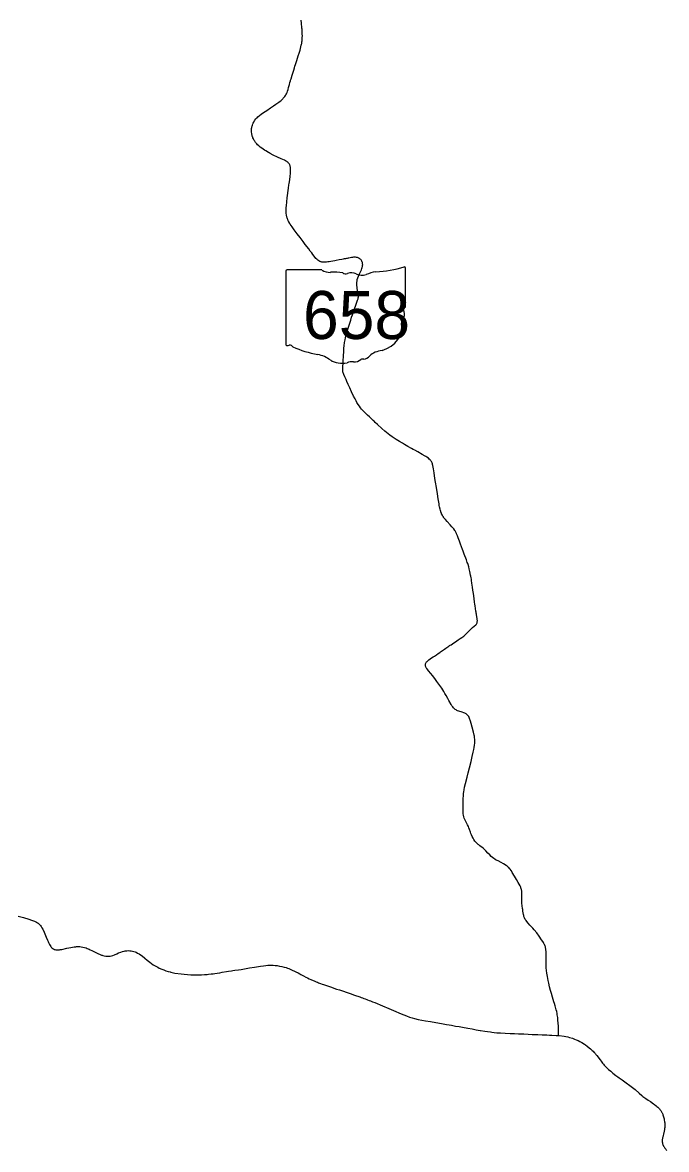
# Model space of a CAD drawing. Extents: x 1913970 to 2397567, y 78841 to 829347.
# Drawn here: x 2199640 to 2214681, y 744108 to 770418 of the extents above; entities that cross this region are included whole.
import ezdxf

# ---------------------------------------------------------------- set-up
doc = ezdxf.new("R2010")
doc.units = 0
doc.layers.add('GM_X_State_Route', color=7, linetype='Continuous')
doc.layers.add('GM_X_State_Shield', color=7, linetype='Continuous')

msp = doc.modelspace()

# ---------------------------------------------------------------- linework, layer by layer
at = {"layer": 'GM_X_State_Route'}
for points in [[(2204992, 767950), (2204993, 767962), (2204997, 767980), (2205001, 767995), (2205009, 768020), (2205022, 768056), (2205028, 768071), (2205040, 768096), (2205047, 768108), (2205061, 768130), (2205069, 768140), (2205090, 768167), (2205109, 768188), (2205118, 768197), (2205139, 768218), (2205172, 768247), (2205212, 768278), (2205271, 768318), (2205345, 768368), (2205432, 768425), (2205502, 768472), (2205559, 768511), (2205626, 768559), (2205657, 768583), (2205679, 768601), (2205701, 768620), (2205720, 768638), (2205731, 768650), (2205747, 768666), (2205765, 768689), (2205781, 768711), (2205793, 768732), (2205806, 768756), (2205818, 768785), (2205830, 768817), (2205843, 768858), (2205856, 768901), (2205874, 768970), (2205886, 769015), (2205897, 769054), (2205902, 769071), (2205911, 769101), (2205937, 769187), (2205959, 769256), (2205975, 769308), (2205991, 769361), (2206003, 769401), (2206016, 769440), (2206045, 769529), (2206080, 769637), (2206101, 769703), (2206123, 769776), (2206144, 769851), (2206152, 769888), (2206158, 769916), (2206161, 769930), (2206166, 769967), (2206168, 769988), (2206172, 770028), (2206175, 770067), (2206176, 770110), (2206175, 770145), (2206175, 770176), (2206174, 770210), (2206172, 770242), (2206169, 770267), (2206167, 770289), (2206165, 770309), (2206163, 770328), (2206157, 770375), (2206153, 770405), (2206146, 770471)], [(2210127, 757400), (2210123, 757426), (2210118, 757454), (2210111, 757494), (2210107, 757517), (2210090, 757598), (2210075, 757664), (2210062, 757712), (2210046, 757763), (2210038, 757789), (2210029, 757815), (2210007, 757876), (2209958, 758005), (2209933, 758073), (2209917, 758117), (2209895, 758175), (2209871, 758239), (2209847, 758306), (2209819, 758384), (2209800, 758432), (2209779, 758480), (2209775, 758488), (2209759, 758522), (2209742, 758551), (2209737, 758559), (2209714, 758594), (2209697, 758617), (2209678, 758640), (2209671, 758648), (2209631, 758692), (2209557, 758768), (2209517, 758812), (2209498, 758835), (2209491, 758844), (2209475, 758866), (2209469, 758877), (2209453, 758904), (2209447, 758914), (2209430, 758949), (2209426, 758959), (2209412, 758994), (2209409, 759001), (2209402, 759024), (2209393, 759058), (2209380, 759113), (2209375, 759144), (2209368, 759183), (2209350, 759299), (2209331, 759416), (2209307, 759565), (2209287, 759688), (2209274, 759774), (2209254, 759902), (2209238, 759996), (2209232, 760039), (2209224, 760076), (2209218, 760102), (2209213, 760118), (2209207, 760135), (2209199, 760152), (2209190, 760169), (2209181, 760181), (2209171, 760195), (2209163, 760205), (2209141, 760226), (2209119, 760245), (2209086, 760268), (2209058, 760287), (2209042, 760297), (2208975, 760336), (2208872, 760393), (2208801, 760431), (2208761, 760453), (2208727, 760472), (2208636, 760523), (2208564, 760564), (2208514, 760594), (2208446, 760635), (2208366, 760686), (2208275, 760745), (2208218, 760784), (2208181, 760812), (2208140, 760845), (2208103, 760877), (2208030, 760943), (2207931, 761034), (2207879, 761083), (2207850, 761110), (2207831, 761128), (2207743, 761212), (2207698, 761255), (2207653, 761298), (2207595, 761356), (2207561, 761392), (2207534, 761425), (2207508, 761460), (2207479, 761503), (2207451, 761548), (2207430, 761585), (2207407, 761629), (2207373, 761696), (2207325, 761797), (2207283, 761889), (2207247, 761970), (2207217, 762036), (2207196, 762084), (2207169, 762147), (2207147, 762199), (2207137, 762222), (2207131, 762238), (2207124, 762265), (2207123, 762280), (2207121, 762292), (2207119, 762335), (2207122, 762390), (2207126, 762456), (2207132, 762544), (2207136, 762603), (2207138, 762639), (2207143, 762737), (2207146, 762790), (2207148, 762813), (2207154, 762871), (2207163, 762946), (2207174, 763011), (2207182, 763055), (2207194, 763104), (2207226, 763212), (2207306, 763471), (2207327, 763538), (2207346, 763597), (2207374, 763678), (2207416, 763800), (2207432, 763846), (2207465, 763935), (2207476, 763968), (2207482, 763993), (2207485, 764015), (2207486, 764034), (2207485, 764047), (2207482, 764068), (2207472, 764125), (2207456, 764212), (2207453, 764241), (2207449, 764280), (2207447, 764321), (2207449, 764349), (2207450, 764362), (2207453, 764382), (2207460, 764419), (2207472, 764458), (2207487, 764498), (2207510, 764551), (2207554, 764643), (2207566, 764675), (2207574, 764696), (2207576, 764706), (2207581, 764725), (2207583, 764735), (2207584, 764750), (2207585, 764759), (2207584, 764781), (2207582, 764797), (2207580, 764808), (2207578, 764816), (2207574, 764827), (2207568, 764843), (2207559, 764859), (2207554, 764866), (2207547, 764876), (2207539, 764886), (2207529, 764895), (2207519, 764903), (2207513, 764907), (2207505, 764912), (2207498, 764916), (2207482, 764923), (2207464, 764929), (2207441, 764934), (2207419, 764937), (2207394, 764937), (2207372, 764937), (2207346, 764933), (2207324, 764929), (2207292, 764924), (2207261, 764918), (2207243, 764915), (2207224, 764911), (2207205, 764908), (2207182, 764904), (2207156, 764899), (2207133, 764894), (2207102, 764888), (2207035, 764875), (2206967, 764862), (2206931, 764855), (2206887, 764848), (2206844, 764840), (2206799, 764832), (2206768, 764828), (2206739, 764825), (2206705, 764822), (2206683, 764821), (2206659, 764822), (2206634, 764825), (2206618, 764829), (2206610, 764831), (2206604, 764833), (2206593, 764837), (2206582, 764842), (2206566, 764851), (2206558, 764856), (2206537, 764870), (2206521, 764884), (2206512, 764892), (2206492, 764913), (2206453, 764961), (2206424, 765000), (2206395, 765039), (2206378, 765061), (2206362, 765082), (2206324, 765131), (2206245, 765239), (2206196, 765304), (2206124, 765400), (2206057, 765488), (2205986, 765582), (2205937, 765648), (2205912, 765682), (2205892, 765712), (2205883, 765725), (2205860, 765764), (2205855, 765773), (2205850, 765783), (2205846, 765792), (2205840, 765806), (2205835, 765817), (2205826, 765839), (2205820, 765858), (2205815, 765873), (2205811, 765889), (2205806, 765909), (2205803, 765928), (2205799, 765957), (2205796, 765982), (2205795, 765998), (2205795, 766020), (2205798, 766066), (2205799, 766099), (2205803, 766141), (2205824, 766326), (2205853, 766549), (2205864, 766627), (2205868, 766659), (2205880, 766746), (2205891, 766832), (2205899, 766896), (2205902, 766950), (2205902, 766965), (2205901, 766994), (2205899, 767022), (2205897, 767039), (2205893, 767058), (2205889, 767073), (2205885, 767085), (2205880, 767097), (2205874, 767109), (2205866, 767122), (2205854, 767137), (2205843, 767149), (2205835, 767156), (2205827, 767162), (2205815, 767171), (2205795, 767183), (2205784, 767190), (2205759, 767202), (2205682, 767237), (2205592, 767278), (2205498, 767325), (2205426, 767361), (2205398, 767375), (2205385, 767382), (2205320, 767419), (2205292, 767437), (2205257, 767461), (2205227, 767482), (2205191, 767510), (2205156, 767541), (2205130, 767566), (2205110, 767588), (2205091, 767610), (2205084, 767620), (2205073, 767634), (2205065, 767645), (2205050, 767667), (2205042, 767682), (2205032, 767700), (2205022, 767724), (2205016, 767740), (2205011, 767752), (2205004, 767776), (2205001, 767788), (2204997, 767804), (2204993, 767824), (2204989, 767855), (2204988, 767889), (2204989, 767921), (2204990, 767938), (2204992, 767950)], [(2212155, 746766), (2212155, 746786), (2212155, 746844), (2212156, 746902), (2212156, 746954), (2212155, 746989), (2212151, 747056), (2212147, 747125), (2212140, 747185), (2212130, 747253), (2212126, 747283), (2212117, 747327), (2212108, 747366), (2212081, 747463), (2212065, 747514), (2212051, 747557), (2212021, 747660), (2211994, 747746), (2211974, 747821), (2211952, 747906), (2211932, 747990), (2211919, 748054), (2211901, 748148), (2211888, 748227), (2211880, 748285), (2211874, 748347), (2211869, 748410), (2211867, 748481), (2211867, 748592), (2211868, 748645), (2211867, 748720), (2211864, 748773), (2211862, 748788), (2211859, 748810), (2211855, 748828), (2211852, 748837), (2211846, 748855), (2211833, 748889), (2211825, 748904), (2211818, 748919), (2211805, 748941), (2211793, 748960), (2211764, 749003), (2211707, 749085), (2211650, 749164), (2211594, 749232), (2211558, 749274), (2211488, 749348), (2211447, 749391), (2211416, 749430), (2211400, 749451), (2211382, 749480), (2211365, 749515), (2211359, 749530), (2211353, 749550), (2211347, 749567), (2211343, 749590), (2211335, 749630), (2211328, 749674), (2211322, 749716), (2211320, 749729), (2211310, 749804), (2211304, 749848), (2211301, 749887), (2211299, 749923), (2211300, 749965), (2211302, 750017), (2211305, 750078), (2211304, 750112), (2211303, 750129), (2211301, 750145), (2211298, 750162), (2211294, 750177), (2211289, 750194), (2211282, 750212), (2211276, 750228), (2211262, 750259), (2211217, 750342), (2211180, 750408), (2211131, 750491), (2211079, 750576), (2211059, 750609), (2211051, 750621), (2211030, 750651), (2211018, 750666), (2210997, 750691), (2210987, 750700), (2210979, 750707), (2210971, 750714), (2210956, 750725), (2210934, 750740), (2210877, 750774), (2210822, 750804), (2210746, 750843), (2210706, 750864), (2210683, 750877), (2210675, 750882), (2210651, 750899), (2210620, 750923), (2210588, 750950), (2210552, 750984), (2210509, 751028), (2210462, 751078), (2210430, 751110), (2210396, 751139), (2210322, 751198), (2210295, 751220), (2210286, 751227), (2210256, 751254), (2210229, 751281), (2210206, 751309), (2210184, 751341), (2210163, 751376), (2210144, 751412), (2210125, 751454), (2210112, 751488), (2210101, 751517), (2210082, 751575), (2210068, 751614), (2210054, 751647), (2210036, 751684), (2209986, 751780), (2209971, 751813), (2209958, 751843), (2209948, 751873), (2209939, 751909), (2209934, 751944), (2209932, 751982), (2209930, 752039), (2209930, 752117), (2209932, 752196), (2209935, 752291), (2209938, 752370), (2209941, 752415), (2209946, 752454), (2209953, 752502), (2209967, 752569), (2209989, 752655), (2210024, 752801), (2210048, 752903), (2210077, 753020), (2210116, 753168), (2210145, 753280), (2210169, 753385), (2210182, 753443), (2210191, 753490), (2210200, 753549), (2210203, 753592), (2210205, 753635), (2210204, 753674), (2210204, 753687), (2210200, 753720), (2210198, 753737), (2210195, 753756), (2210190, 753781), (2210172, 753853), (2210141, 753970), (2210118, 754054), (2210102, 754110), (2210082, 754169), (2210072, 754194), (2210061, 754214), (2210051, 754228), (2210035, 754248), (2210017, 754264), (2210000, 754277), (2209975, 754290), (2209949, 754300), (2209912, 754314), (2209831, 754338), (2209800, 754350), (2209787, 754356), (2209765, 754368), (2209748, 754379), (2209728, 754395), (2209705, 754418), (2209689, 754439), (2209670, 754465), (2209653, 754493), (2209601, 754587), (2209574, 754634), (2209535, 754704), (2209506, 754754), (2209480, 754797), (2209457, 754836), (2209431, 754877), (2209389, 754937), (2209319, 755034), (2209271, 755103), (2209216, 755173), (2209177, 755221), (2209122, 755286), (2209104, 755306), (2209082, 755337), (2209071, 755353), (2209063, 755370), (2209058, 755379), (2209055, 755390), (2209052, 755404), (2209051, 755416), (2209051, 755426), (2209053, 755442), (2209058, 755458), (2209066, 755474), (2209076, 755489), (2209089, 755504), (2209104, 755519), (2209127, 755537), (2209158, 755559), (2209194, 755583), (2209230, 755606), (2209262, 755627), (2209285, 755642), (2209309, 755659), (2209350, 755686), (2209387, 755712), (2209406, 755725), (2209429, 755741), (2209497, 755787), (2209531, 755812), (2209572, 755840), (2209595, 755856), (2209616, 755871), (2209628, 755880), (2209649, 755893), (2209680, 755914), (2209714, 755936), (2209754, 755961), (2209819, 756003), (2209864, 756034), (2209902, 756062), (2209944, 756095), (2209977, 756124), (2210013, 756154), (2210047, 756190), (2210152, 756292), (2210191, 756326), (2210227, 756358), (2210241, 756374), (2210250, 756386), (2210257, 756404), (2210261, 756421), (2210262, 756428), (2210263, 756435), (2210264, 756450), (2210264, 756460), (2210263, 756472), (2210261, 756489), (2210258, 756510), (2210255, 756526), (2210253, 756540), (2210249, 756561), (2210247, 756573), (2210241, 756605), (2210238, 756626), (2210234, 756649), (2210231, 756674), (2210221, 756740), (2210214, 756796), (2210206, 756842), (2210200, 756889), (2210187, 756973), (2210171, 757090), (2210160, 757167), (2210151, 757239), (2210145, 757283), (2210138, 757332), (2210129, 757393), (2210127, 757400)], [(2199542, 749556), (2199662, 749521), (2199785, 749483), (2199853, 749460), (2199894, 749444), (2199918, 749435), (2199934, 749428), (2199967, 749412), (2199988, 749400), (2200003, 749390), (2200025, 749372), (2200039, 749357), (2200058, 749336), (2200074, 749313), (2200083, 749300), (2200095, 749279), (2200112, 749247), (2200143, 749182), (2200162, 749140), (2200194, 749061), (2200224, 748991), (2200236, 748963), (2200246, 748937), (2200253, 748923), (2200270, 748890), (2200284, 748867), (2200299, 748845), (2200309, 748831), (2200320, 748820), (2200327, 748813), (2200348, 748798), (2200357, 748792), (2200368, 748785), (2200379, 748780), (2200396, 748775), (2200420, 748769), (2200446, 748767), (2200468, 748767), (2200482, 748768), (2200505, 748770), (2200520, 748773), (2200561, 748780), (2200677, 748805), (2200769, 748823), (2200809, 748831), (2200844, 748837), (2200882, 748842), (2200901, 748843), (2200926, 748844), (2200951, 748844), (2200979, 748843), (2201011, 748839), (2201051, 748832), (2201088, 748823), (2201123, 748813), (2201153, 748802), (2201173, 748794), (2201197, 748784), (2201224, 748771), (2201256, 748756), (2201337, 748714), (2201401, 748680), (2201452, 748657), (2201482, 748646), (2201498, 748641), (2201515, 748635), (2201551, 748627), (2201584, 748622), (2201613, 748620), (2201643, 748619), (2201686, 748623), (2201720, 748629), (2201747, 748637), (2201785, 748651), (2201840, 748674), (2201884, 748695), (2201933, 748713), (2201979, 748729), (2202016, 748739), (2202037, 748743), (2202056, 748746), (2202077, 748748), (2202114, 748750), (2202144, 748748), (2202177, 748744), (2202208, 748739), (2202242, 748730), (2202273, 748720), (2202297, 748710), (2202329, 748694), (2202363, 748674), (2202398, 748651), (2202432, 748625), (2202496, 748572), (2202553, 748525), (2202610, 748478), (2202651, 748447), (2202691, 748421), (2202706, 748412), (2202754, 748385), (2202767, 748378), (2202799, 748361), (2202835, 748344), (2202853, 748336), (2202874, 748327), (2202939, 748299), (2202991, 748280), (2203042, 748264), (2203089, 748251), (2203106, 748247), (2203164, 748234), (2203199, 748227), (2203342, 748207), (2203414, 748198), (2203492, 748191), (2203569, 748186), (2203638, 748183), (2203667, 748183), (2203684, 748183), (2203714, 748182), (2203745, 748183), (2203773, 748183), (2203817, 748185), (2203889, 748189), (2203922, 748191), (2203951, 748195), (2203982, 748198), (2204045, 748205), (2204064, 748207), (2204092, 748211), (2204134, 748217), (2204190, 748226), (2204245, 748235), (2204301, 748244), (2204401, 748260), (2204452, 748268), (2204523, 748278), (2204554, 748284), (2204602, 748291), (2204686, 748303), (2204748, 748312), (2204825, 748327), (2204941, 748349), (2205058, 748367), (2205197, 748389), (2205272, 748398), (2205327, 748405), (2205366, 748408), (2205392, 748409), (2205446, 748409), (2205496, 748407), (2205539, 748404), (2205587, 748399), (2205643, 748390), (2205695, 748380), (2205748, 748367), (2205798, 748353), (2205829, 748341), (2205858, 748331), (2205909, 748309), (2205956, 748288), (2205979, 748277), (2206023, 748255), (2206075, 748228), (2206116, 748207), (2206142, 748193), (2206203, 748161), (2206261, 748131), (2206294, 748115), (2206338, 748094), (2206371, 748078), (2206392, 748069), (2206410, 748061), (2206431, 748052), (2206449, 748044), (2206500, 748023), (2206528, 748012), (2206555, 748001), (2206601, 747983), (2206641, 747969), (2206669, 747959), (2206763, 747926), (2206858, 747893), (2206912, 747873), (2206975, 747852), (2207043, 747831), (2207296, 747745), (2207391, 747712), (2207520, 747668), (2207546, 747659), (2207578, 747647), (2207615, 747633), (2207640, 747625), (2207679, 747609), (2207695, 747604), (2207738, 747588), (2207765, 747577), (2207817, 747556), (2207872, 747535), (2208047, 747461), (2208198, 747398), (2208304, 747353), (2208481, 747275), (2208544, 747249), (2208606, 747225), (2208680, 747198), (2208739, 747179), (2208793, 747164), (2208880, 747145), (2208967, 747127), (2209054, 747111), (2209167, 747092), (2209382, 747055), (2209425, 747048), (2209541, 747027), (2209608, 747015), (2209660, 747006), (2209757, 746989), (2209841, 746975), (2209915, 746961), (2210038, 746940), (2210142, 746921), (2210235, 746903), (2210329, 746887), (2210338, 746885), (2210439, 746869), (2210504, 746860), (2210569, 746851), (2210602, 746847), (2210657, 746841), (2210716, 746834), (2210801, 746828), (2210916, 746822), (2211027, 746818), (2211132, 746815), (2211223, 746810), (2211286, 746807), (2211348, 746804), (2211449, 746800), (2211541, 746795), (2211600, 746792), (2211633, 746791), (2211678, 746790), (2211781, 746786), (2211885, 746781), (2211947, 746779), (2212003, 746777), (2212101, 746771), (2212155, 746766), (2212176, 746765), (2212293, 746751), (2212332, 746745), (2212373, 746736), (2212417, 746724), (2212483, 746703), (2212518, 746691)], [(2212518, 746691), (2212532, 746686), (2212575, 746669), (2212619, 746649), (2212660, 746628), (2212706, 746603), (2212768, 746564), (2212786, 746551), (2212827, 746521), (2212874, 746484), (2212906, 746457), (2212929, 746437), (2212947, 746420), (2212967, 746401), (2212984, 746383), (2212998, 746369), (2213010, 746355), (2213021, 746342), (2213033, 746326), (2213051, 746303), (2213129, 746199), (2213152, 746169), (2213171, 746144), (2213189, 746120), (2213207, 746099), (2213226, 746077), (2213241, 746060), (2213257, 746043), (2213271, 746029), (2213288, 746013), (2213306, 745995), (2213328, 745975), (2213378, 745932), (2213430, 745890), (2213500, 745837), (2213541, 745806), (2213578, 745778), (2213644, 745732), (2213739, 745665), (2213825, 745602), (2213889, 745552), (2213947, 745505), (2214041, 745422), (2214105, 745366), (2214129, 745347), (2214155, 745328), (2214202, 745297), (2214253, 745262), (2214311, 745224), (2214378, 745176), (2214401, 745159), (2214439, 745128), (2214456, 745113), (2214476, 745096), (2214504, 745068), (2214515, 745056), (2214527, 745042), (2214547, 745016), (2214557, 745001), (2214567, 744986), (2214573, 744974), (2214579, 744962), (2214586, 744946), (2214592, 744930), (2214598, 744914), (2214603, 744895), (2214616, 744848), (2214623, 744819), (2214630, 744790), (2214634, 744764), (2214637, 744750), (2214640, 744732), (2214641, 744719), (2214642, 744707), (2214643, 744693), (2214644, 744675), (2214644, 744654), (2214642, 744638), (2214640, 744617), (2214637, 744599), (2214633, 744573), (2214624, 744531), (2214609, 744465), (2214600, 744431), (2214593, 744398), (2214590, 744377), (2214586, 744355), (2214584, 744341), (2214583, 744329), (2214582, 744317), (2214582, 744307), (2214582, 744299), (2214583, 744289), (2214583, 744283), (2214584, 744277), (2214585, 744270), (2214586, 744263), (2214588, 744252), (2214591, 744240), (2214596, 744225), (2214599, 744215), (2214603, 744207), (2214607, 744197), (2214610, 744190), (2214615, 744182), (2214624, 744168), (2214646, 744134), (2214662, 744113), (2214681, 744086)]]:
    msp.add_lwpolyline(points, dxfattribs=at)
at = {"layer": 'GM_X_State_Shield'}
for p, q in [((2205787, 764612), (2205787, 762910)), ((2206635, 764641), (2205815, 764641)), ((2208589, 763793), (2208589, 764683)), ((2208588, 763793), (2208589, 763793))]:
    msp.add_line(p, q, dxfattribs=at)
for centre, major_axis, start_param, end_param in [((2205819, 764615), (32.5, 0), 1.712693, 3.28349), ((2206831, 764838), (315, 0), 4.042523, 4.731795), ((2206935, 763686), (1130, 0), 1.404758, 1.657858), ((2207970, 764121), (598, 0), 1.699011, 2.107814), ((2207591, 766960), (2971, 0), 4.814394, 5.042369), ((2208558, 764687), (31.2, 0), 6.141152, 7.989035), ((2207191, 764624), (90.8, 0), 3.836095, 5.185415), ((2207325, 764427), (189, 0), 0.950623, 2.079405), ((2207569, 764697), (227, 0), 4.081561, 5.145723), ((2208582, 763728), (48.3, 0), 1.883978, 3.671073), ((2208274, 763615), (290, 0), 5.934695, 6.695948), ((2208555, 763790), (33.4, 0), 5.05454, 6.418171), ((2207757, 763308), (743, 0), 5.101752, 6.440018), ((2208701, 763421), (211, 0), 2.387724, 3.262537), ((2205819, 762907), (32.7, 0), 3.00124, 4.508301), ((2205824, 763081), (250, 0), 4.665946, 4.897461), ((2205876, 762812), (90.1, 0), 0.519207, 1.627899), ((2207013, 764341), (2146, 0), 4.195997, 4.488961), ((2208071, 762433), (407, 0), 1.647645, 2.488434), ((2206373, 762146), (671, 0), 0.823519, 1.323587), ((2207100, 762804), (426, 0), 4.026481, 4.996735), ((2207346, 762216), (350, 0), 1.495662, 1.94098), ((2207377, 762676), (227, 0), 4.691044, 5.507374), ((2207582, 762512), (63.9, 0), 1.147584, 2.315152), ((2207555, 762746), (240, 0), 4.937069, 5.64225)]:
    msp.add_ellipse(centre, major_axis=major_axis, ratio=0.8, start_param=start_param, end_param=end_param, dxfattribs=at)

# ---------------------------------------------------------------- texts
msp.add_text('658', height=1120.7, dxfattribs=at).set_placement((2206192, 763030))

doc.saveas('drawing.dxf')
